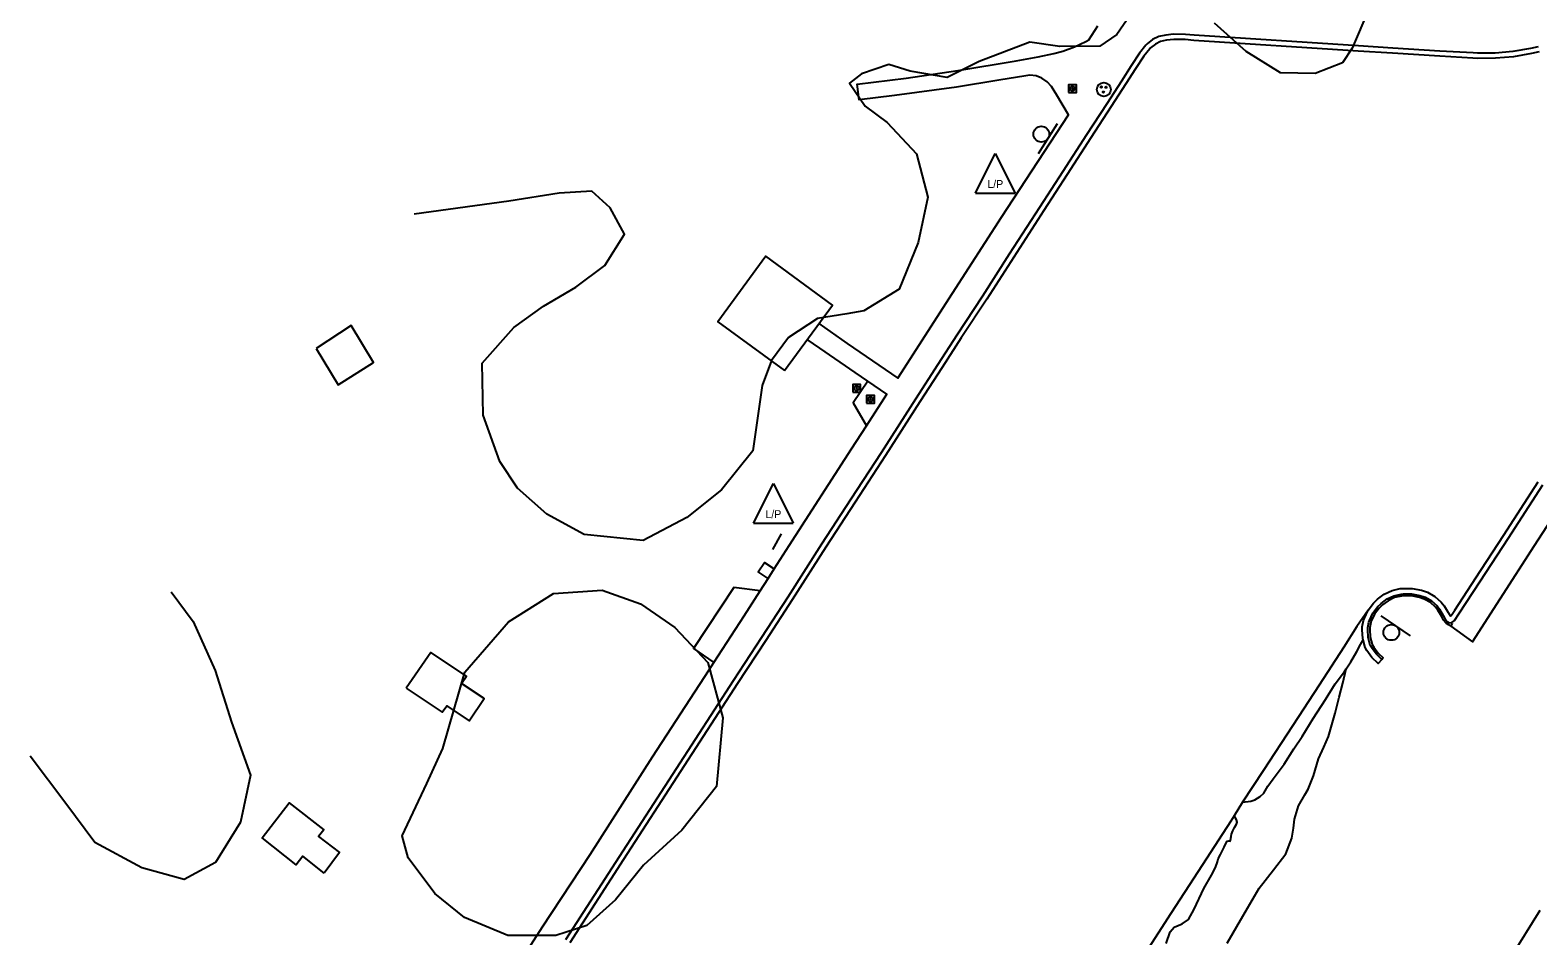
# Model space of a CAD drawing. Extents: x 2161152 to 2175754, y 602179 to 617749.
# Drawn here: x 2161801.1 to 2162182.3, y 604117.6 to 604346.6 of the extents above; entities that cross this region are included whole.
import ezdxf

# ---------------------------------------------------------------- set-up
doc = ezdxf.new("R2010")
doc.units = 0
for name, color, linetype in [('RD_EX_Bldg', 7, 'Continuous'), ('RD_EX_BldgApp_Sign', 7, 'Continuous'), ('RD_EX_Conc_Curb', 7, 'Continuous'), ('RD_EX_Conc_Gutter', 7, 'Continuous'), ('RD_EX_Conc_Sidewalk', 7, 'Continuous'), ('RD_EX_Conc_Slab', 7, 'Continuous'), ('RD_EX_DR_Inlet', 7, 'Continuous'), ('RD_EX_Misc', 7, 'Continuous'), ('RD_EX_Parking_Asphalt', 7, 'Continuous'), ('RD_EX_Parking_Conc', 7, 'Continuous'), ('RD_EX_Parking_Unpaved', 7, 'Continuous'), ('RD_EX_Road', 7, 'Continuous'), ('RD_EX_UT', 7, 'Continuous'), ('RD_EX_VEG', 7, 'Continuous')]:
    doc.layers.add(name, color=color, linetype=linetype)

msp = doc.modelspace()

# ---------------------------------------------------------------- linework, layer by layer
at = {"layer": 'RD_EX_Bldg'}
msp.add_lwpolyline([(2161991.82, 604260.52), (2162003.98, 604277.12), (2161987.15, 604289.45), (2161974.99, 604272.85), (2161991.82, 604260.52)], dxfattribs=at)
at = {"layer": 'RD_EX_BldgApp_Sign'}
for p, q in [((2162056.07, 604315.43), (2162060.89, 604323.04)), ((2161988.85, 604215.25), (2161991.12, 604219.28)), ((2162150.16, 604193.45), (2162142.71, 604198.51))]:
    msp.add_line(p, q, dxfattribs=at)
for centre in [(2162056.78, 604320.33), (2162145.28, 604194.31)]:
    msp.add_circle(centre, 2, dxfattribs=at)
at = {"layer": 'RD_EX_Conc_Curb'}
for points in [[(2162182.38, 604342.4), (2162180.49, 604342.02), (2162176.04, 604341.23), (2162171.55, 604340.83), (2162167.04, 604340.83), (2162165.98, 604340.88), (2162157.59, 604341.34), (2162145.68, 604342.1), (2162137.02, 604342.63), (2162095.42, 604345.35), (2162093.25, 604345.55), (2162090.21, 604345.59), (2162088.24, 604345.4), (2162086.52, 604345.01), (2162084.92, 604344.25), (2162083.53, 604343.16), (2162083.19, 604342.8), (2162081.62, 604340.82), (2162079.46, 604337.57), (2162077.04, 604333.77), (2162073.33, 604328.04), (2162068.18, 604320.14), (2162062.21, 604310.85), (2162056.34, 604301.76), (2162048.69, 604289.95), (2162041.88, 604279.34), (2162035.44, 604269.52), (2162030.63, 604262.04), (2162024.99, 604253.3), (2162016.27, 604239.77), (2162008.62, 604227.99), (2162001.22, 604216.6), (2161992.65, 604203.24), (2161986.02, 604192.99), (2161978.89, 604182.09), (2161950.02, 604137.58), (2161936.42, 604116.52)], [(2162160.64, 604196.66), (2162160.34, 604195.88), (2162159.76, 604196.26), (2162159.16, 604196.63), (2162158.5, 604197.42), (2162157.99, 604198.38), (2162157.06, 604199.94), (2162156.49, 604200.66), (2162155.17, 604201.86), (2162153.63, 604202.75), (2162152.4, 604203.18), (2162150.37, 604203.55), (2162148.29, 604203.55), (2162147.85, 604203.51), (2162146.09, 604203.1), (2162144.47, 604202.34), (2162143.02, 604201.26), (2162142.19, 604200.45), (2162141.04, 604198.91), (2162140.21, 604197.15), (2162140.07, 604196.8), (2162139.84, 604195.53), (2162139.81, 604195.01), (2162139.94, 604193.07), (2162140.43, 604191.23), (2162140.82, 604190.54), (2162141.92, 604189.09), (2162143.25, 604187.87), (2162143.01, 604187.61), (2162142.91, 604187.5), (2162141.43, 604188.88), (2162140.24, 604190.52), (2162139.96, 604191.04), (2162139.44, 604192.99), (2162139.31, 604195.01), (2162139.34, 604195.59), (2162139.59, 604196.94), (2162139.75, 604197.35), (2162140.61, 604199.17), (2162141.82, 604200.78), (2162142.7, 604201.64), (2162144.21, 604202.78), (2162145.92, 604203.58), (2162147.77, 604204), (2162148.26, 604204.05), (2162150.41, 604204.05), (2162152.53, 604203.66), (2162153.84, 604203.21), (2162155.46, 604202.26), (2162156.85, 604201), (2162157.47, 604200.23), (2162158.43, 604198.63), (2162158.92, 604197.7), (2162159.49, 604197.01), (2162159.89, 604196.77), (2162160.59, 604196.81), (2162161.15, 604197.21), (2162161.22, 604197.3), (2162162.39, 604199.03), (2162167.81, 604207.33), (2162174.85, 604218.09), (2162183.58, 604231.61)]]:
    msp.add_lwpolyline(points, dxfattribs=at)
at = {"layer": 'RD_EX_Conc_Gutter'}
for points in [[(2162182.69, 604341.12), (2162180.73, 604340.72), (2162176.22, 604339.92), (2162171.61, 604339.51), (2162167.01, 604339.5), (2162165.91, 604339.56), (2162157.51, 604340.03), (2162145.6, 604340.78), (2162136.93, 604341.31), (2162095.32, 604344.04), (2162093.18, 604344.23), (2162090.27, 604344.27), (2162088.45, 604344.09), (2162086.95, 604343.76), (2162085.62, 604343.12), (2162084.42, 604342.18), (2162084.19, 604341.93), (2162082.69, 604340.04), (2162080.56, 604336.85), (2162078.15, 604333.06), (2162074.44, 604327.32), (2162069.29, 604319.42), (2162063.32, 604310.14), (2162057.43, 604301.05), (2162049.79, 604289.24), (2162042.97, 604278.63), (2162036.54, 604268.81), (2162031.73, 604261.33), (2162026.09, 604252.59), (2162017.37, 604239.06), (2162009.71, 604227.27), (2162002.32, 604215.89), (2161993.75, 604202.53), (2161987.12, 604192.27), (2161979.98, 604181.38), (2161951.12, 604136.87), (2161937.52, 604115.8)], [(2162142.91, 604187.5), (2162141.95, 604186.47), (2162140.37, 604187.95), (2162139.05, 604189.77), (2162138.65, 604190.51), (2162138.13, 604192.47), (2162138.05, 604192.76), (2162137.9, 604195), (2162137.95, 604195.76), (2162138.23, 604197.32), (2162138.46, 604197.91), (2162139.4, 604199.9), (2162140.76, 604201.71), (2162141.78, 604202.71), (2162143.48, 604203.99), (2162145.46, 604204.91), (2162147.54, 604205.39), (2162148.19, 604205.46), (2162150.54, 604205.46), (2162152.89, 604205.02), (2162154.43, 604204.49), (2162156.3, 604203.41), (2162157.88, 604201.97), (2162158.63, 604201.03), (2162159.65, 604199.32), (2162159.96, 604198.75), (2162160.07, 604198.56), (2162160.21, 604198.5), (2162160.39, 604198.62), (2162160.85, 604199.22), (2162161.33, 604199.98), (2162166.63, 604208.1), (2162173.68, 604218.86), (2162182.4, 604232.37)]]:
    msp.add_lwpolyline(points, dxfattribs=at)
at = {"layer": 'RD_EX_Conc_Sidewalk'}
for points in [[(2162000.54, 604272.43), (2162007.66, 604267.41), (2162020.47, 604258.59), (2162034.32, 604280.08), (2162046.73, 604299.35), (2162063.65, 604325.21), (2162060.73, 604330.21), (2162059.37, 604332.4), (2162058.29, 604333.59), (2162056.95, 604334.49), (2162055.44, 604335.04), (2162053.84, 604335.21), (2162052.83, 604335.11), (2162046.05, 604333.95), (2162035.36, 604332.22), (2162019.63, 604330.07), (2162010.72, 604328.98), (2162010.24, 604333.01), (2162022.61, 604334.51), (2162035.66, 604336.46), (2162050.44, 604338.84), (2162055.96, 604339.86), (2162059.95, 604340.71), (2162062.24, 604341.35), (2162065.19, 604342.39), (2162068, 604343.74), (2162068.76, 604344.17), (2162071.04, 604347.72)], [(2161885.85, 604049.93), (2161889.53, 604056.03), (2161894.87, 604064.78), (2161909.87, 604087.73), (2161921.27, 604105.3), (2161930.67, 604119.84), (2161942.67, 604138.13), (2161958.45, 604162.85), (2161972.76, 604184.87), (2161973.98, 604186.74), (2161981.65, 604198.54), (2161985.68, 604204.85), (2161987.67, 604207.96), (2161989.23, 604210.4), (2161992.99, 604216.27), (2162008.82, 604240.74), (2162012.59, 604246.56), (2162017.75, 604254.53), (2162012.87, 604257.89), (2162009.71, 604260.07), (2162000.75, 604266.2), (2161997.61, 604268.42)], [(2162160.34, 604195.88), (2162165.84, 604191.89), (2162172.84, 604202.82), (2162181.5, 604216.26), (2162193.4, 604234.6)]]:
    msp.add_lwpolyline(points, dxfattribs=at)
at = {"layer": 'RD_EX_Conc_Slab'}
for points in [[(2161873.39, 604266.1), (2161878.94, 604256.92), (2161887.88, 604262.56), (2161882.28, 604271.92), (2161873.39, 604266.1)], [(2162012.87, 604257.89), (2162009.24, 604252.35), (2162012.59, 604246.56)], [(2161987.67, 604207.96), (2161985.18, 604209.66), (2161986.77, 604212.03), (2161989.23, 604210.4)], [(2161985.68, 604204.85), (2161979.02, 604205.68), (2161968.8, 604190.25), (2161973.98, 604186.74)], [(2161896.2, 604180.18), (2161905.3, 604174.15), (2161906.44, 604175.78), (2161912.07, 604171.97), (2161915.92, 604177.61), (2161910.13, 604181.4), (2161911.45, 604183.22), (2161902.41, 604189.24), (2161896.2, 604180.18)], [(2161875.4, 604133.43), (2161870.03, 604137.7), (2161868.38, 604135.54), (2161859.72, 604142.34), (2161866.56, 604151.2), (2161875.33, 604144.4), (2161874, 604142.69), (2161879.31, 604138.62), (2161875.4, 604133.43)]]:
    msp.add_lwpolyline(points, dxfattribs=at)
at = {"layer": 'RD_EX_DR_Inlet'}
for centre, radius in [((2162072.58, 604331.63), 1.75), ((2162071.92, 604332.26), 0.175), ((2162072.5, 604330.97), 0.175), ((2162073.14, 604332.19), 0.175)]:
    msp.add_circle(centre, radius, dxfattribs=at)
at = {"layer": 'RD_EX_Misc'}
for points in [[(2162063.68, 604330.84), (2162065.68, 604330.84), (2162065.68, 604332.84), (2162063.68, 604332.84), (2162063.68, 604330.84)], [(2162064.08, 604331.84), (2162064.1, 604331.99), (2162064.15, 604332.14), (2162064.25, 604332.26), (2162064.37, 604332.35), (2162064.51, 604332.42), (2162064.66, 604332.44), (2162064.81, 604332.43), (2162064.95, 604332.37), (2162065.08, 604332.29), (2162065.18, 604332.17), (2162065.25, 604332.03), (2162065.28, 604331.88), (2162065.28, 604331.84)], [(2162065.28, 604331.84), (2162065.26, 604331.69), (2162065.2, 604331.55), (2162065.11, 604331.43), (2162064.99, 604331.33), (2162064.85, 604331.27), (2162064.7, 604331.24), (2162064.54, 604331.26), (2162064.4, 604331.31), (2162064.27, 604331.4), (2162064.17, 604331.52), (2162064.11, 604331.65), (2162064.08, 604331.8), (2162064.08, 604331.84)], [(2162064.58, 604331.84), (2162064.6, 604331.9), (2162064.65, 604331.94), (2162064.71, 604331.94), (2162064.76, 604331.9), (2162064.78, 604331.84)], [(2162064.78, 604331.84), (2162064.76, 604331.78), (2162064.71, 604331.75), (2162064.65, 604331.75), (2162064.6, 604331.78), (2162064.58, 604331.84)], [(2162009.09, 604255.05), (2162011.09, 604255.05), (2162011.09, 604257.05), (2162009.09, 604257.05), (2162009.09, 604255.05)], [(2162009.49, 604256.05), (2162009.51, 604256.21), (2162009.56, 604256.35), (2162009.66, 604256.47), (2162009.78, 604256.57), (2162009.92, 604256.63), (2162010.07, 604256.65), (2162010.22, 604256.64), (2162010.36, 604256.59), (2162010.49, 604256.5), (2162010.59, 604256.38), (2162010.66, 604256.24), (2162010.69, 604256.09), (2162010.69, 604256.05)], [(2162010.69, 604256.05), (2162010.67, 604255.9), (2162010.61, 604255.76), (2162010.52, 604255.64), (2162010.4, 604255.54), (2162010.26, 604255.48), (2162010.11, 604255.45), (2162009.95, 604255.47), (2162009.81, 604255.52), (2162009.68, 604255.61), (2162009.58, 604255.73), (2162009.52, 604255.87), (2162009.49, 604256.02), (2162009.49, 604256.05)], [(2162009.99, 604256.05), (2162010.01, 604256.11), (2162010.06, 604256.15), (2162010.12, 604256.15), (2162010.17, 604256.11), (2162010.19, 604256.05)], [(2162010.19, 604256.05), (2162010.17, 604256), (2162010.12, 604255.96), (2162010.06, 604255.96), (2162010.01, 604256), (2162009.99, 604256.05)], [(2162012.59, 604252.26), (2162014.59, 604252.26), (2162014.59, 604254.26), (2162012.59, 604254.26), (2162012.59, 604252.26)], [(2162012.99, 604253.26), (2162013.01, 604253.41), (2162013.07, 604253.56), (2162013.16, 604253.68), (2162013.28, 604253.77), (2162013.42, 604253.84), (2162013.57, 604253.86), (2162013.73, 604253.85), (2162013.87, 604253.79), (2162014, 604253.71), (2162014.1, 604253.59), (2162014.16, 604253.45), (2162014.19, 604253.3), (2162014.19, 604253.26)], [(2162014.19, 604253.26), (2162014.17, 604253.11), (2162014.12, 604252.97), (2162014.02, 604252.84), (2162013.9, 604252.75), (2162013.76, 604252.69), (2162013.61, 604252.66), (2162013.46, 604252.68), (2162013.32, 604252.73), (2162013.19, 604252.82), (2162013.09, 604252.93), (2162013.02, 604253.07), (2162012.99, 604253.22), (2162012.99, 604253.26)], [(2162013.49, 604253.26), (2162013.51, 604253.32), (2162013.56, 604253.36), (2162013.62, 604253.36), (2162013.67, 604253.32), (2162013.69, 604253.26)], [(2162013.69, 604253.26), (2162013.67, 604253.2), (2162013.62, 604253.17), (2162013.56, 604253.17), (2162013.51, 604253.2), (2162013.49, 604253.26)]]:
    msp.add_lwpolyline(points, dxfattribs=at)
at = {"layer": 'RD_EX_Parking_Asphalt'}
for points in [[(2162107.65, 604151.34), (2162109.79, 604151.6), (2162110.75, 604151.96), (2162112.1, 604152.85), (2162113.07, 604153.64), (2162114.08, 604155.4), (2162115.41, 604157.25), (2162118.19, 604160.96), (2162120.64, 604164.89), (2162122.7, 604167.99), (2162125.49, 604172.53), (2162128.63, 604177.34), (2162131.08, 604181.28), (2162133.41, 604184.43), (2162133.88, 604185.13), (2162135.03, 604186.86), (2162136.53, 604189.46), (2162137.53, 604191.24), (2162138.13, 604192.47)], [(2162088.36, 604115.67), (2162089.4, 604118.59), (2162090.37, 604119.79), (2162092.4, 604120.61), (2162093.96, 604121.67), (2162095.41, 604124.29), (2162097.86, 604129.54), (2162099.83, 604132.89), (2162100.86, 604134.83), (2162101.34, 604136.32), (2162101.53, 604137.06), (2162102.12, 604138.12), (2162102.53, 604138.96), (2162102.99, 604140.03), (2162103.35, 604140.79), (2162103.75, 604141.48), (2162104.2, 604141.58), (2162104.5, 604141.51), (2162104.65, 604141.76), (2162104.81, 604142.69), (2162104.84, 604143.26), (2162105.17, 604144.17), (2162105.61, 604144.93), (2162106.17, 604145.78), (2162106.29, 604146.34), (2162106.13, 604146.93), (2162105.54, 604147.91)]]:
    msp.add_lwpolyline(points, dxfattribs=at)
at = {"layer": 'RD_EX_Parking_Conc'}
msp.add_lwpolyline([(2162139.4, 604199.9), (2162136.56, 604195.78), (2162133.25, 604190.58), (2162127.03, 604181.01), (2162120.36, 604170.8), (2162112.85, 604159.27), (2162107.65, 604151.34), (2162105.54, 604147.91), (2162104.69, 604146.54), (2162096.43, 604133.86), (2162089.52, 604123.18), (2162079.91, 604108.33)], dxfattribs=at)
at = {"layer": 'RD_EX_Parking_Unpaved'}
msp.add_lwpolyline([(2162103.74, 604115.7), (2162107.71, 604122.54), (2162111.89, 604129.61), (2162115.48, 604134.26), (2162118.59, 604138.28), (2162120.16, 604142.26), (2162120.58, 604144.77), (2162120.79, 604147.04), (2162121.81, 604150.42), (2162123.4, 604153.23), (2162124.25, 604154.65), (2162125.62, 604158.06), (2162126.89, 604162.36), (2162128.18, 604165.29), (2162129.43, 604167.95), (2162131.09, 604173.89), (2162132.12, 604177.97), (2162133.03, 604181.44), (2162133.88, 604185.13)], dxfattribs=at)
at = {"layer": 'RD_EX_Road'}
msp.add_lwpolyline([(2162182.84, 604123.94), (2162175.52, 604112.15)], dxfattribs=at)
at = {"layer": 'RD_EX_UT'}
for p, q in [((2162040.15, 604305.44), (2162045.15, 604315.44)), ((2162045.15, 604315.44), (2162050.15, 604305.44)), ((2162040.15, 604305.44), (2162050.15, 604305.44)), ((2161984.03, 604221.95), (2161989.03, 604231.95)), ((2161989.03, 604231.95), (2161994.03, 604221.95)), ((2161984.03, 604221.95), (2161994.03, 604221.95))]:
    msp.add_line(p, q, dxfattribs=at)
at = {"layer": 'RD_EX_VEG'}
for points in [[(2162079.25, 604350.41), (2162075.84, 604345.53), (2162071.54, 604342.57), (2162061.47, 604342.54), (2162053.91, 604343.58), (2162041.04, 604338.73), (2162032.97, 604334.69), (2162023.58, 604336.3), (2162018.24, 604337.91), (2162011.35, 604335.61), (2162008.25, 604333.21), (2162012.21, 604327.4), (2162017.78, 604323.29), (2162025.23, 604315.36), (2162028.12, 604304.36), (2162025.6, 604292.95), (2162020.81, 604281.16), (2162011.92, 604275.63), (2162007.61, 604274.86), (2162000.2, 604273.72), (2161992.81, 604268.9), (2161988.55, 604263.12), (2161986.19, 604256.77), (2161983.86, 604240.2), (2161975.93, 604230.41), (2161967.13, 604223.4), (2161956.06, 604217.57), (2161941.16, 604219.11), (2161931.75, 604224.24), (2161924.31, 604230.82), (2161919.83, 604237.55), (2161915.62, 604249.29), (2161915.37, 604262.38), (2161923.36, 604271.47), (2161930.87, 604276.79), (2161939.06, 604281.63), (2161946.41, 604287.1), (2161951.4, 604295.01), (2161947.72, 604301.69), (2161943.16, 604305.93), (2161934.89, 604305.38), (2161922.15, 604303.36), (2161898.19, 604300.12)], [(2162139.57, 604351.98), (2162135.36, 604342.07), (2162132.95, 604338.4), (2162126.01, 604335.7), (2162117.24, 604335.82), (2162108.61, 604341.27), (2162100.59, 604348.44)], [(2161836.73, 604204.61), (2161842.27, 604197.03), (2161847.88, 604184.7), (2161851.99, 604171.6), (2161856.78, 604158.18), (2161854.26, 604146.33), (2161847.94, 604136.08), (2161840.07, 604131.85), (2161829.3, 604134.73), (2161817.48, 604141.19), (2161810.11, 604151.06), (2161801.09, 604163.01)], [(2161901.39, 604156.08), (2161905.47, 604164.93), (2161910.99, 604184.27), (2161922.01, 604196.98), (2161933.41, 604204.17), (2161945.7, 604205.01), (2161955.4, 604201.53), (2161964.13, 604195.54), (2161972.44, 604186.72), (2161976.27, 604172.74), (2161974.66, 604155.36), (2161965.91, 604144.26), (2161956.21, 604135.46), (2161949.14, 604126.66), (2161941.88, 604120.16), (2161934.04, 604117.69), (2161921.88, 604117.65), (2161910.93, 604122.19), (2161903.42, 604128.24), (2161896.68, 604137.3), (2161895.16, 604142.9), (2161901.39, 604156.08)]]:
    msp.add_lwpolyline(points, dxfattribs=at)

# ---------------------------------------------------------------- texts
at = {"layer": 'RD_EX_UT'}
for p in [(2162043.14, 604306.72), (2161987.02, 604223.23)]:
    msp.add_text('L/P', height=2, dxfattribs=at).set_placement(p)

doc.saveas('drawing.dxf')
